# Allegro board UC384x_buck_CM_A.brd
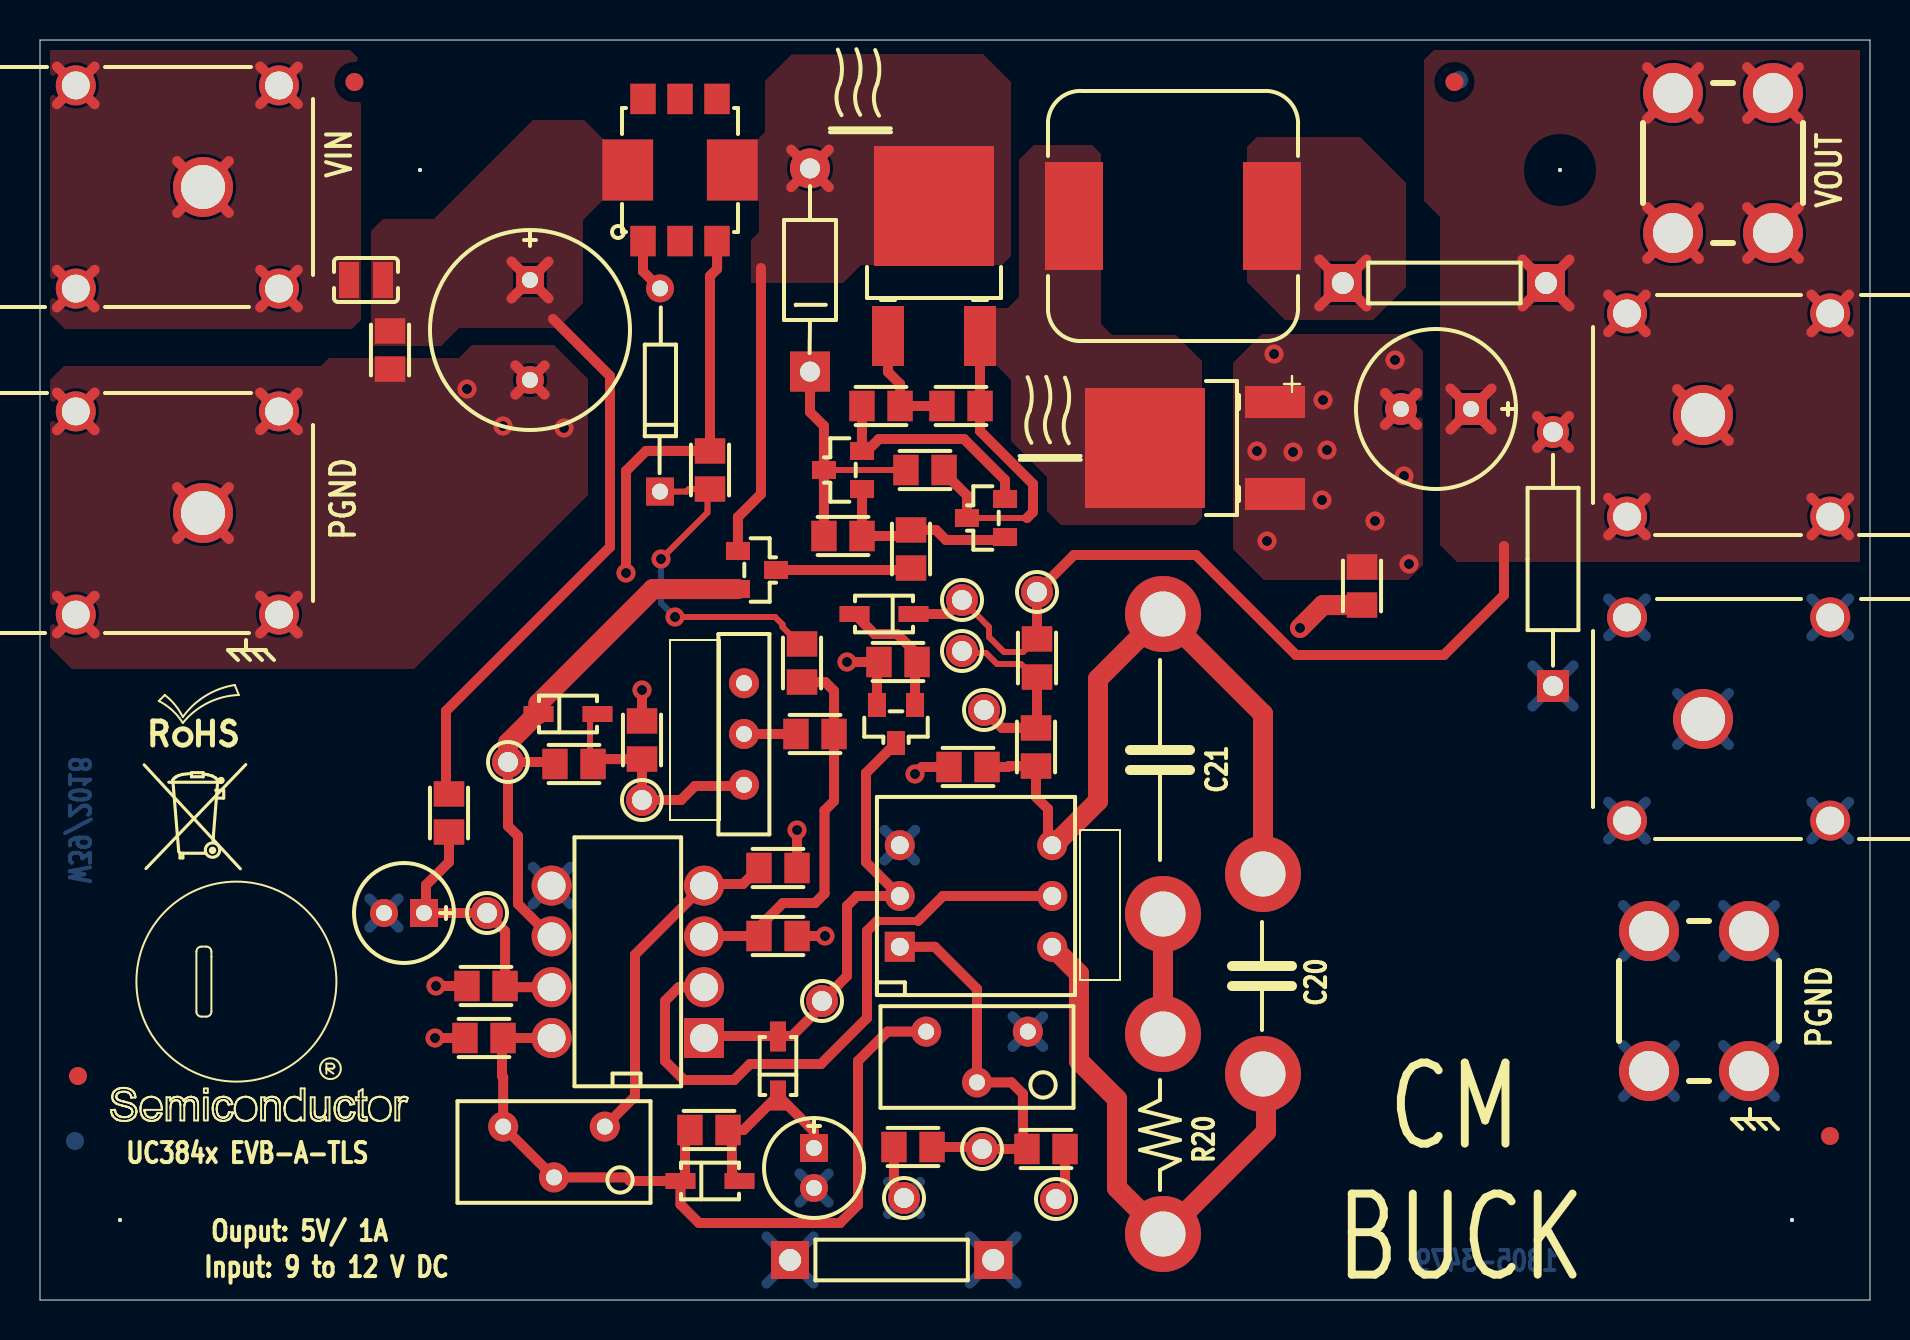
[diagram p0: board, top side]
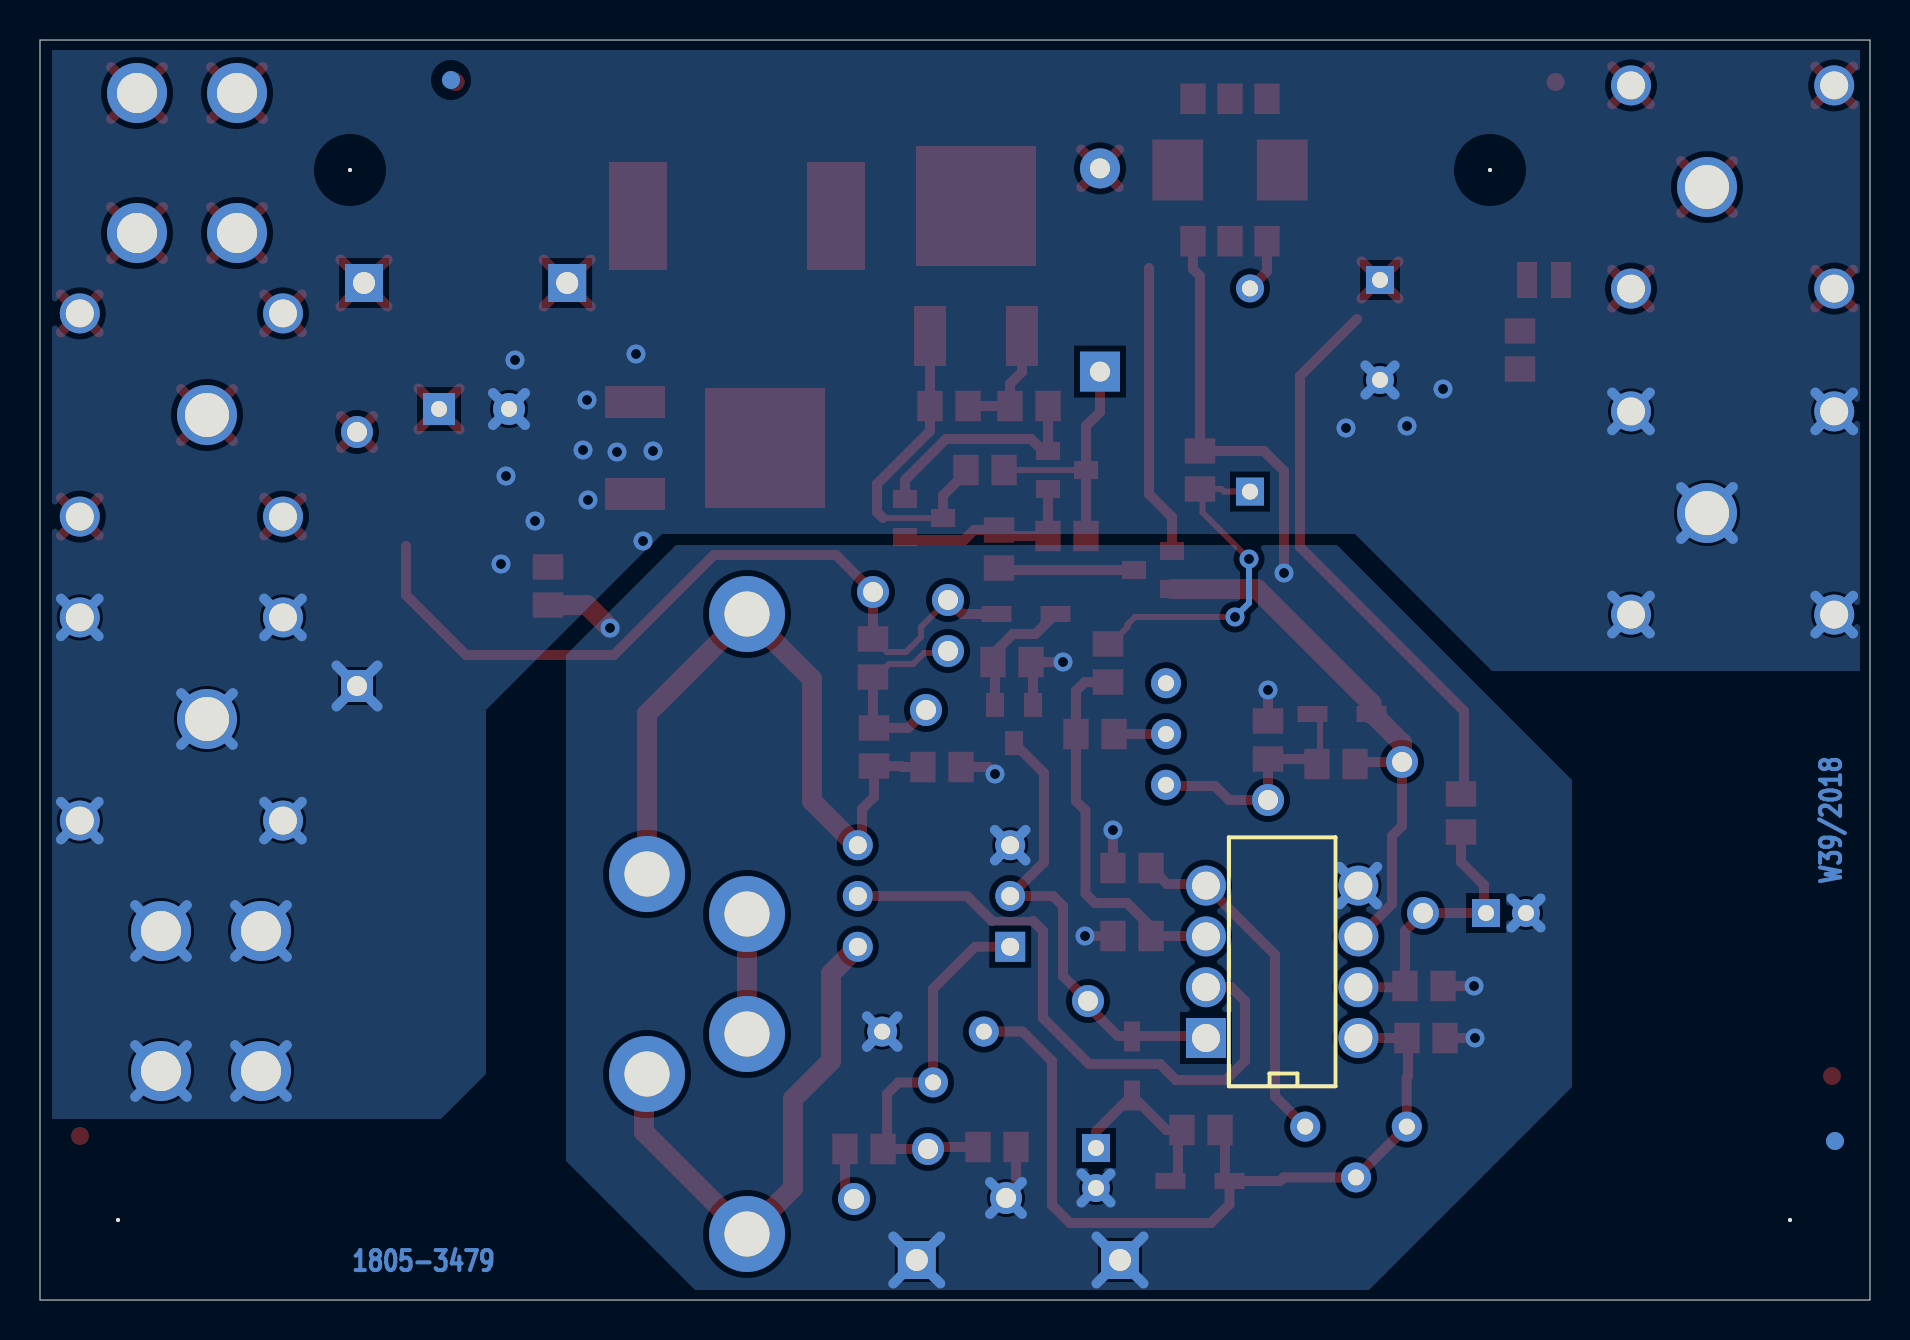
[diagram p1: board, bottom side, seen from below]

Outline 91.5 x 63 mm; copper layers: TOP, IN1, IN2, BOTTOM. Coordinates in mm from the lower left corner of the outline.
Outline path: 0,63 0,0 91.5,0 91.5,63 0,63

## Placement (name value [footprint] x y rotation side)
ACM_H  TEST POINT  [TP]  50.8 5.05 180 top
ACM_L  TEST POINT  [TP]  43.2 5.1 180 top
C1  100nF  [0805]  22.2 13.1 180 top
C1A  D  [PLOT_5380598-2]  56.15 34.3 270 top
C1B  D  [PLOT_5380598-2]  56.15 19.3 270 top
C2  2.2nF  [0805]  36.9 21.6 0 top
C2A  D  [PLOT_5380598-2]  61.15 21.3 270 top
C2B  D  [PLOT_5380598-2]  61.15 11.3 270 top
C3  2.2uF  [CAPA_CH_D5_H11_P2]  18.2 19.35 180 top
C6  220uF  [CAPA_CH_D8_H12_P3V5]  69.8 44.55 180 top
C7  100nF  [0805]  22.3 15.7 180 top
C8  100nF  [0805]  43.65 7.65 180 top
C9  2.2uF  [0805]  50.3 7.55 180 top
C10  100pF  [0805]  36.9 18.2 0 top
C11  2.2nF  [0805]  30.1 28 90 top
C12  100uF /6v3  [CAPA_CH_D5_H11_P2]  38.7 6.6 270 top
C13  470uF  [CAPA_CH_D10_H13_P5]  24.5 48.5 270 top
C14  1uF  [0805]  17.5 47.5 270 top
C18  0.1uF  [0805]  44.25 41.5 0 top
CB1  target_cms  [MIRE_LOW]  1.75 7.95 180 bottom
CB2  target_cms  [MIRE_LOW]  70.95 61 180 bottom
CB3  target_cms  [MIRE_LOW]  1.9 11.2 0 top
CB4  target_cms  [MIRE_LOW]  70.72 60.9 0 top
CB5  target_cms  [MIRE_LOW]  89.5 8.2 0 top
CB6  target_cms  [MIRE_LOW]  15.72 60.9 0 top
COMP  TEST POINT  [TP]  39.1 14.95 180 top
D1  1N4148w  [SOD123]  26.4 29.3 0 top
D2  1N4148w  [SOD123]  33.5 5.95 0 top
D3  MBRD1045T4G  [DPAK_TO252]  56.85 42.6 90 top
D4  1N4148w  [SOD123]  36.9 11.7 90 top
D6  MMSZ6V2T1G  [SOD123]  42.2 34.3 180 top
D7  1N965  [DO35]  31 45.5 90 top
D8  1N5817  [DO41]  38.5 51.5 90 top
DRV  TEST POINT  [TP]  23.4 26.9 180 top
J1A  SLB4-I/90_R  [BANANE_4MM_SLB4]  8.15 55.65 180 top
J1B  SLB4-I/90_B  [BANANE_4MM_SLB4]  8.15 39.35 180 top
J1C  SLB4-I/90_R  [BANANE_4MM_SLB4]  83.15 44.25 0 top
J1D  SLB4-I/90_B  [BANANE_4MM_SLB4]  83.15 29.05 0 top
J2A  Screw_terminal  [PC_7701]  84.15 56.85 0 top
J2B  Screw_terminal  [PC_7701]  82.95 14.95 0 top
L1  100uH-1.7A  [SELF_WE-PD-1260]  56.65 54.2 90 top
L2  2.2uH  [SELF_SRN2009]  16.3 51 0 top
NOREF  -  [unnamed]  87.6 4 0 top
NOREF#2  -  [#2]  91.5 0 90 top
NOREF#3  -  [unnamed]  4 4 0 top
NOREF#4  -  [#2]  0 63 0 top
NOREF#5  -  [unnamed]  76 56.5 0 top
NOREF#6  -  [#2]  91.5 0 90 top
NOREF#7  -  [#2]  -181.6 -74.35 0 top
NOREF#8  -  [#2]  -114.15 -47.45 0 top
NOREF#9  -  [#2]  87.6 4 0 top
NOREF#10  -  [unnamed]  19 56.5 0 top
NOREF#11  -  [#2]  283.55 -63.75 180 bottom
P1  10K  [POTAR_12T_3266W]  46.85 12.15 180 top
P2  20K  [POTAR_12T_3266W]  25.7 7.4 180 top
Q1  NTD5865NLT4G  [DPAK_TO252]  44.7 53.1 0 top
Q2  MMBT2222A  [SOT23]  42.8 28.8 0 top
Q3  MMBT2222A  [SOT23]  40.15 41.5 270 top
Q6  MMBT2907A  [SOT23]  47.3 39.1 270 top
Q7  BSS138LT1G  [SOT23]  35.85 36.5 90 top
R1  10K  [0805]  49.8 27.65 90 top
R2  4.7K  [0805]  38.1 31.85 270 top
R2A  D  [PLOT_5380598-2]  56.15 13.3 270 top
R2B  D  [PLOT_5380598-2]  56.15 3.3 270 top
R3  60  [0805]  33.5 41.5 270 top
R4  22K  [0805]  26.7 26.8 0 top
R5  10R  [0805]  20.45 24.35 90 top
R6  33K  [0805]  38.75 28.3 180 top
R7  10K  [0805]  46.4 26.65 0 top
R8  10R  [0805]  49.85 32.1 90 top
R11  0R  [0805]  66.1 35.7 90 top
R12  1K / 0.5W  [RC21U]  75.65 37.05 90 top
R13  1.5K  [0805]  33.45 8.5 180 top
R14  1K  [0805]  42.9 31.9 0 top
R15  47K  [0805]  46.05 44.7 180 top
R16  10R  [0805]  42.05 44.7 0 top
R17  2.2K  [0805]  40.15 38.2 0 top
R18  100  [0805]  43.55 37.55 270 top
RAMP  TEST POINT  [TP]  30.1 25 180 top
S1  Strap  [JUMPER400H]  75.3 50.85 180 top
S2  Strap  [JUMPER400H]  37.5 2 0 top
SW1  DPDT  [SW_76SD01ST]  46.8 20.2 0 top
SW2  DPDT  [SWITCH-1K2]  35.2 28.3 90 top
T1  KMP_53100C  [MURATA_5300]  32 56.5 0 top
U1  UC3845B  [DIP8_SUP]  33.2 13.1 180 top
VA  TEST POINT  [TP]  47.2 29.5 0 top
VA_  TEST POINT  [TP]  46.1 32.45 0 top
VB  TEST POINT  [TP]  49.85 35.4 0 top
VB_  TEST POINT  [TP]  46.1 35 0 top
VCC  TEST POINT  [TP]  22.35 19.35 180 top
VSET  TEST POINT  [TP]  47.1 7.55 180 top

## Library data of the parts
ACM_H ACM_L COMP DRV RAMP S1 S2 VA VA_ VB VB_ VCC VSET = TEST POINT_0
C1 C2 C7-C11 C14 C18 = C
C1A C1B C2A C2B R2A R2B = T POINT R_0
C3 C12 = CAP POL
C6 C13 = C_elect_0
CB1-CB6 = target_cms
D1 = D1N4148_1
D2 D4 = D1N4148_2
D3 = dual_diodeAAK
D6 = DIODE SCHOTTKY_0
D7 = 1N965_0
D8 = 1N5817_0
J1A J1B J1C J1D = HEADER 1_0
J2A J2B = 4 HEADER_0
L1 = CHOKE
L2 = L
P1 P2 = RESISTOR VAR
Q1 = NMOS_2
Q2 Q3 = 2N2222A_0
Q6 = 2N2907A_0
Q7 = NMOS_1
R1-R8 R11-R18 = R
SW1 = SW DPDT/SM_0
SW2 = SW SPST
T1 = KMP_0
U1 = UC3845B

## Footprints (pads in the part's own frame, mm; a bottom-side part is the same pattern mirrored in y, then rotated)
0805
  rect 1.27x1.524 smd: 1(-0.953,0) 2(0.953,0)
BANANE_4MM_SLB4
  round 3 hole 2.2: 1(0,0)
  round 2 hole 1.4: 2(-3.8,5.08) 3(-3.8,-5.08) 4(6.36,5.08) 5(6.36,-5.08)
CAPA_CH_D5_H11_P2
  rect 1.4x1.4 hole 0.8: 1(-1,0)
  round 1.4 hole 0.8: 2(1,0)
CAPA_CH_D8_H12_P3V5
  rect 1.6x1.6 hole 0.8: 1(-1.75,0)
  round 1.6 hole 0.8: 2(1.75,0)
CAPA_CH_D10_H13_P5
  rect 1.4x1.4 hole 0.8: 1(-2.5,0)
  round 1.4 hole 0.8: 2(2.5,0)
DIP8_SUP
  rect 2x2 hole 1.4: 1(0,0)
  round 2 hole 1.4: 2(0,-2.54) 3(0,-5.08) 4(0,-7.62) 5(7.62,-7.62) 6(7.62,-5.08) 7(7.62,-2.54) 8(7.62,0)
DO35
  rect 1.4x1.4 hole 0.8: 1(-5.08,0)
  round 1.4 hole 0.8: 2(5.08,0)
DO41
  rect 2x2 hole 1: 1(-5.08,0)
  round 2 hole 1: 2(5.08,0)
DPAK_TO252
  rect 1.6x3 smd: 1(-2.3,-4.9) 3(2.3,-4.9)
  rect 6x6 smd: 2(0,1.6)
JUMPER400H
  rect 1.9x1.9 hole 1.1: 1(0,0) 2(10.16,0)
MIRE_LOW
  round 0.9 smd: 1(0,0)
MURATA_5300
  rect 1.27x1.524 smd: 1(-1.85,-3.555) 2(0,-3.555) 3(1.85,-3.555) 4(1.85,3.555) 5(0,3.555) 6(-1.85,3.555)
  rect 2.54x3.05 smd: 7(2.615,0) 8(-2.615,0)
PC_7701
  round 3 hole 2: 1(-2.5,-3.5) 2(2.5,-3.5) 3(2.5,3.5) 4(-2.5,3.5)
PLOT_5380598-2
  round 3.8 hole 2.25: 1(0,0)
POTAR_12T_3266W
  round 1.5 hole 0.8: 1(-2.54,-1.27) 2(0,1.27) 3(2.54,-1.27)
RC21U
  rect 1.6x1.6 hole 1: 1(-6.35,0)
  round 1.6 hole 1: 2(6.35,0)
SELF_SRN2009
  rect 1x1.8 smd: 1(-0.85,0) 2(0.85,0)
SELF_WE-PD-1260
  rect 5.4x2.9 smd: 1(0,4.95) 2(0,-4.95)
SOD123
  rect 1.5x0.8 smd: 1(-1.475,0) 2(1.475,0)
SOT23
  rect 0.9x1.2 smd: 1(0.953,0.953) 2(-0.953,0.953) 3(0,-0.953)
SW_76SD01ST
  rect 1.5x1.5 hole 0.9: 1(-3.81,-2.54)
  round 1.5 hole 0.9: 2(-3.81,2.54) 11(3.81,-2.54) 22(3.81,2.54) C1(-3.81,0) C2(3.81,0)
SWITCH-1K2
  round 1.5 hole 0.8: 1(-2.54,0) 2(0,0) 3(2.54,0)
TP
  round 1.6 hole 1: 1(0,0)
unnamed
  round 0.2 hole 3 unplated: (0,0)

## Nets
GND_EARTH: ACM_L.1 C1.2 C2.2 C3.2 C7.2 C8.2 C10.2 C11.2 C12.2 P1.1(A) Q2.2(EMITTER) R3.1 R7.1 R11.1 R14.1 S2.1 S2.2 SW1.2(NO2) T1.3 U1.5(GND)
GND_SIGNAL: C6.2(-) C13.2(-) C14.2 D3.1(A1) D3.3(A2) J1B.1 J1B.2 J1B.3 J1B.4 J1B.5 J1D.1 J1D.2 J1D.3 J1D.4 J1D.5 J2B.1 J2B.2 J2B.3 J2B.4 R11.2 R12.1
VCC: C3.1 C7.1 R5.1 U1.7(VCC) VCC.1
CMP: COMP.1 D4.2 Q2.3(COLLECTOR) SW1.C1(COMMON1) U1.1(EA)
DRV: D1.1 DRV.1 Q7.2(S) R4.1 U1.6(DRV)
REF: C1.1 D2.1 P1.3(B) P2.2(WIPER) P2.3(B) R13.2 U1.8(REF)
VOUT: C6.1(+) D6.1(CATHODE) J1C.1 J1C.2 J1C.3 J1C.4 J1C.5 J2A.1 J2A.2 J2A.3 J2A.4 R8.2 R12.2 S1.1 VB.1 VB_.1
N12289703: C13.1(+) C14.1 L2.2 R5.2 T1.8
N12295463: C2.1 P2.1(A) U1.4(RT/CT)
N12295845: C10.1 R2.2 R6.1 U1.3(IS)
N12296076: D7.1(CATHODE) R2.1 R3.2
N12296104: SW1.C2(COMMON2) U1.2(FB)
N12296437: C11.1 D1.2 R4.2 RAMP.1 SW2.1
N12297349: R1.2 R8.1 VA.1 VA_.1
N12298127: C1A.1(TP) C2A.1(TP) R1.1 R7.2 SW1.22(NC2)
N12298463: C8.1 C9.2 P1.2(WIPER) SW1.1(NO1) VSET.1
N12299817: C1B.1(TP) R2A.1(TP)
N12299821: C2B.1(TP) R2B.1(TP) SW1.11(NC1)
N12301916: ACM_H.1 C9.1
N12517793: J1A.1 J1A.2 J1A.3 J1A.4 J1A.5 L2.1
N12518756: D8.2 Q1.2(D) Q7.1(G) T1.7
N12518780: Q7.3(D) R18.2
N12519113: D7.2(ANODE) T1.1
N12519598: Q3.1(BASE) Q6.1(BASE) R17.2 R18.1
N12520738: C18.1 D8.1 Q3.3(COLLECTOR) R17.1
N12521657: Q3.2(EMITTER) Q6.2(EMITTER) R16.1
N12521671: Q1.1(G) R15.2 R16.2
N12521759: C18.2 D3.2(C) L1.1 Q1.3(S) Q6.3(COLLECTOR) R15.1
N12522225: L1.2 S1.2
N12524308: C12.1 D2.2 D4.1 R13.1
N12524692: D6.2(ANODE) Q2.1(BASE) R14.2
N122961380: R6.2 SW2.2

Pads without a net: CB1 1; CB2 1; CB3 1; CB4 1; CB5 1; CB6 1; SW2 3; T1 2 4 5 6

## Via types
v1: diameter 0.95, hole 0.5, TOP to BOTTOM, 25 vias

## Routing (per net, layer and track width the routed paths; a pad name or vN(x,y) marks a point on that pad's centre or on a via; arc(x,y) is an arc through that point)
GND_EARTH: length 80.3
  TOP w0.5: C1.2 v1(19.75,13.1) ; C10.2 v1(39.25,18.2) ; Q2.2 41.85,31.8 R14.1 v1(40.35,31.9) ; C2.2 v1(37.85,23.5) ; R7.1 44.1,26.65 v1(43.75,26.3) ; ACM_L.1 42.7,5.6 C8.2 ; v1(29.3,36.35) 29.3,41.45 30.3,42.45 R3.1 33.5,51.2 33.85,51.55 33.85,52.94 T1.3 ; C11.2 v1(30.1,30.5) ; C7.2 v1(19.8,15.7)
  TOP w1: v1(63,33.6) 64.15,34.75 R11.1
  BOTTOM w0.5: 24.64,21.66 U1.5 ; U1.5 26.52,19.78 ; U1.5 26.52,21.66 ; U1.5 24.64,19.78 ; ACM_L.1 44,4.3 ; ACM_L.1 42.4,4.3 ; ACM_L.1 42.4,5.9 ; ACM_L.1 44,5.9 ; C12.2 39.43,6.33 ; C12.2 37.97,4.87 ; C12.2 37.97,6.33 ; C12.2 39.43,4.87 ; 48.63,12.66 P1.1 ; P1.1 50.15,12.66 ; P1.1 48.63,14.18 ; P1.1 50.15,14.18 ; 42.23,21.98 SW1.2 ; SW1.2 43.75,23.5 ; SW1.2 43.75,21.98 ; SW1.2 42.23,23.5 ; S2.2 48.84,3.18 ; S2.2 46.48,0.82 ; S2.2 48.84,0.82 ; S2.2 46.48,3.18 ; 36.32,3.18 S2.1 ; S2.1 38.68,0.82 ; S2.1 38.68,3.18 ; S2.1 36.32,0.82 ; 16.47,18.62 C3.2 ; C3.2 17.93,18.62 ; C3.2 16.47,20.08 ; C3.2 17.93,20.08
GND_SIGNAL: length 138.3
  TOP w0.5: 67.25,45.35 C6.2 ; C6.2 68.85,45.35 ; C6.2 67.25,43.75 ; C6.2 68.85,43.75 ; J1B.5 2.73,43.49 ; J1B.5 2.73,45.37 ; J1B.5 0.85,43.49 ; J1B.5 0.85,45.37 ; J1B.4 2.73,35.21 ; J1B.4 0.85,35.21 ; J1B.4 0.85,33.33 ; J1B.4 2.73,33.33 ; 11.01,43.49 J1B.3 ; J1B.3 12.89,43.49 ; J1B.3 12.89,45.37 ; J1B.3 11.01,45.37 ; 11.01,35.21 J1B.2 ; J1B.2 11.01,33.33 ; J1B.2 12.89,33.33 ; J1B.2 12.89,35.21 ; J1B.1 9.44,38.06 ; J1B.1 6.86,40.64 ; J1B.1 9.44,40.64 ; J1B.1 6.86,38.06 ; 23.77,45.27 C13.2 ; C13.2 23.77,46.73 ; C13.2 25.23,46.73 ; C13.2 25.23,45.27
  BOTTOM w0.5: J1B.5 2.73,45.37 ; J1B.5 2.73,43.49 ; J1B.5 0.85,43.49 ; J1B.5 0.85,45.37 ; 78.41,33.19 J1D.2 ; J1D.2 80.29,33.19 ; J1D.2 80.29,35.07 ; J1D.2 78.41,35.07 ; J1B.4 2.73,33.33 ; J1B.4 0.85,33.33 ; J1B.4 0.85,35.21 ; J1B.4 2.73,35.21 ; 88.57,24.91 J1D.5 ; J1D.5 88.57,23.03 ; J1D.5 90.45,23.03 ; J1D.5 90.45,24.91 ; 79.16,12.74 J2B.1 ; J2B.1 81.74,10.16 ; J2B.1 81.74,12.74 ; J2B.1 79.16,10.16 ; 11.01,35.21 J1B.2 ; J1B.2 12.89,35.21 ; J1B.2 11.01,33.33 ; J1B.2 12.89,33.33 ; J1D.3 80.29,24.91 ; J1D.3 78.41,24.91 ; J1D.3 78.41,23.03 ; J1D.3 80.29,23.03 ; J1D.1 84.44,30.34 ; J1D.1 81.86,30.34 ; J1D.1 81.86,27.76 ; J1D.1 84.44,27.76 ; 79.16,17.16 J2B.4 ; J2B.4 81.74,17.16 ; J2B.4 81.74,19.74 ; J2B.4 79.16,19.74 ; 84.16,17.16 J2B.3 ; J2B.3 86.74,19.74 ; J2B.3 86.74,17.16 ; J2B.3 84.16,19.74 ; J1B.3 12.89,45.37 ; J1B.3 12.89,43.49 ; J1B.3 11.01,43.49 ; J1B.3 11.01,45.37 ; 74.62,29.67 R12.1 ; R12.1 76.68,29.67 ; R12.1 74.62,31.73 ; R12.1 76.68,31.73 ; J1D.4 90.45,33.19 ; J1D.4 90.45,35.07 ; J1D.4 88.57,33.19 ; J1D.4 88.57,35.07 ; C6.2 68.85,45.35 ; C6.2 68.85,43.75 ; C6.2 67.25,45.35 ; C6.2 67.25,43.75 ; 23.77,46.73 C13.2 ; C13.2 25.23,45.27 ; C13.2 25.23,46.73 ; C13.2 23.77,45.27 ; J2B.2 86.74,10.16 ; J2B.2 84.16,10.16 ; J2B.2 84.16,12.74 ; J2B.2 86.74,12.74 ; J1B.1 9.44,40.64 ; J1B.1 6.86,38.06 ; J1B.1 6.86,40.64 ; J1B.1 9.44,38.06
  vias: v1(21.35,45.55) v1(23.15,43.7) v1(26.2,43.6) v1(60.85,42.45) v1(61.35,37.95) v1(61.7,47.3) v1(62.65,42.4) v1(64.1,40) v1(64.15,45) v1(64.35,42.5) v1(66.75,38.95) v1(67.75,47) v1(68.2,41.2) v1(68.45,36.8)
VCC: length 14.1
  TOP w0.5: U1.7 23.31,15.64 C7.1 23.25,18.45 VCC.1 C3.1 19.3,19.45 19.3,20.75 20.45,21.9 R5.1
CMP: length 23.9
  TOP w0.5: 36.88,13.2 33.3,13.2 U1.1 ; 36.88,13.2 37.6,13.2 39.1,14.7 COMP.1 40.35,16.2 40.35,19.7 40.85,20.2 SW1.C1 41.3,21.89 41.3,26.35 Q2.3 ; 36.88,13.2 36.9,13.18
DRV: length 28
  TOP w0.5: U1.6 25.52,18.18 23.9,19.8 23.9,23.2 23.4,23.7 DRV.1 25.65,26.9 R4.1
  TOP w1: Q7.2 30.65,35.55 24.93,29.82 D1.1 24.85,29.3 23.4,27.85 DRV.1
REF: length 41.7
  TOP w0.5: U1.8 C1.1 23.1,13.05 23.1,11.2 23.16,11.14 P2.3 P2.2 29.32,6.13 29.5,5.95 D2.1 ; D2.1 32.25,6.18 32.25,8.25 R13.2 ; D2.1 32.02,4.78 32.95,3.85 40,3.85 40.9,4.75 40.9,11.95 42.37,13.42 P1.3
VOUT: length 115.2
  TOP w0.3: R8.2 49.8,33.05 49.15,32.4 48.2,32.4 47.45,33.15 47.45,33.65 VB_.1
  TOP w0.5: 74.12,49.67 S1.1 ; S1.1 74.12,52.03 ; S1.1 76.48,52.03 ; S1.1 76.48,49.67 ; J1C.1 84.44,42.96 ; J1C.1 81.86,42.96 ; J1C.1 81.86,45.54 ; J1C.1 84.44,45.54 ; 88.57,48.39 J1C.4 ; J1C.4 90.45,48.39 ; J1C.4 88.57,50.27 ; J1C.4 90.45,50.27 ; J2A.1 82.94,54.64 ; J2A.1 82.94,52.06 ; J2A.1 80.36,52.06 ; J2A.1 80.36,54.64 ; R12.2 76.45,44.2 ; R12.2 74.85,42.6 ; R12.2 74.85,44.2 ; R12.2 76.45,42.6 ; 70.52,45.58 C6.1 ; C6.1 72.58,45.58 ; C6.1 72.58,43.52 ; C6.1 70.52,43.52 ; 85.36,52.06 J2A.2 ; J2A.2 87.94,54.64 ; J2A.2 87.94,52.06 ; J2A.2 85.36,54.64 ; 78.41,48.39 J1C.2 ; J1C.2 80.29,50.27 ; J1C.2 78.41,50.27 ; J1C.2 80.29,48.39 ; 78.41,40.11 J1C.3 ; J1C.3 78.41,38.23 ; J1C.3 80.29,38.23 ; J1C.3 80.29,40.11 ; J2A.3 87.94,59.06 ; J2A.3 85.36,59.06 ; J2A.3 85.36,61.64 ; J2A.3 87.94,61.64 ; 80.36,61.64 J2A.4 ; J2A.4 80.36,59.06 ; J2A.4 82.94,59.06 ; J2A.4 82.94,61.64 ; 88.57,38.23 J1C.5 ; J1C.5 90.45,40.11 ; J1C.5 88.57,40.11 ; J1C.5 90.45,38.23 ; 73.2,37.7 73.2,35.25 70.2,32.25 62.8,32.25 57.8,37.25 51.7,37.25 VB.1 R8.2 ; VB_.1 45.4,34.3 D6.1
N12289703: length 33.6
  TOP w0.5: 25.65,49.05 28.5,46.2 28.5,37.65 20.3,29.45 20.3,25.45 R5.2 ; C13.1 25.43,50.07 ; C13.1 23.57,51.93 ; C13.1 23.57,50.07 ; C13.1 25.43,51.93
N12295463: length 17.2
  TOP w0.5: C2.1 35.15,20.8 33.28,20.8 U1.4 29.75,17.27 29.75,10.18 P2.1
N12295845: length 19.4
  TOP w0.5: 35.7,18.2 33.22,18.2 U1.3 ; 35.7,18.2 C10.1 ; 35.7,18.2 35.7,18.4 37.15,19.85 38.75,19.85 39.23,20.33 39.23,24.48 39.7,24.95 R6.1 39.7,30.46 39.26,30.9 R2.2
N12296076: length 17.2
  TOP w0.3: v1(31.05,37.05) 33.37,39.37 33.37,40.55 ; D7.1 32.31,40.42 32.44,40.55 33.37,40.55 ; R3.2 33.37,40.55 ; R2.1 37.97,32.8 37.13,33.65 37.13,33.78 36.75,34.15 v1(31.75,34.15)
  BOTTOM w0.3: v1(31.05,37.05) 31.05,34.85 v1(31.75,34.15)
N12296104: length 31.3
  TOP w0.4: 41.85,18.95 43.9,18.95
  TOP w0.5: U1.2 31.94,15.64 31.25,14.95 31.25,11.95 32.2,11 34.7,11 35.5,11.8 39.05,11.8 41.35,14.1 41.35,18.45 41.85,18.95 ; 43.9,18.95 45.15,20.2 SW1.C2
N12296437: length 12.7
  TOP w0.3: R4.2 27.5,26.95 27.5,28.93 D1.2
  TOP w0.5: SW2.1 35.14,25.7 32.75,25.7 32.05,25 RAMP.1 C11.1 27.9,27.05 R4.2
N12297349: length 9.8
  TOP w0.3: VA_.1 46.2,32.35 47.3,32.35 47.85,31.8 49.05,31.8 49.7,31.15 R8.1
  TOP w0.5: VA.1 48.1,28.6 R1.2 49.85,28.65 R8.1
N12298127: length 35.7
  TOP w0.5: SW1.22 50.4,22.95 50.4,24.55 49.8,25.15 R1.1 48.44,26.7 48.39,26.65 R7.2
  TOP w1: SW1.22 50.69,22.74 52.9,24.95 52.9,31.05 C1A.1 61.15,29.3 C2A.1
N12298463: length 19.6
  TOP w0.5: C9.2 49.15,7.75 49.15,10.3 48.57,10.88 P1.2 46.85,15.55 44.74,17.66 SW1.1 ; C9.2 49.39,7.59 ; C9.2 VSET.1 47,7.65 C8.1
N12299817: length 6
  TOP w1: C1B.1 R2A.1
N12299821: length 26.9
  TOP w1: SW1.11 51.95,16.32 51.95,11.95 53.85,10.05 53.85,5.6 R2B.1 56.2,3.3 61.3,8.4 61.3,11.15 C2B.1
N12301916: length 2.7
  TOP w0.5: ACM_H.1 51.25,5.5 C9.1
N12517793: length 28.6
  TOP w0.5: 11.01,49.63 J1A.2 ; J1A.2 12.89,51.51 ; J1A.2 12.89,49.63 ; J1A.2 11.01,51.51 ; J1A.4 2.73,51.51 ; J1A.4 0.85,49.63 ; J1A.4 0.85,51.51 ; J1A.4 2.73,49.63 ; J1A.5 2.73,59.79 ; J1A.5 2.73,61.67 ; J1A.5 0.85,61.67 ; J1A.5 0.85,59.79 ; 11.01,61.67 J1A.3 ; J1A.3 11.01,59.79 ; J1A.3 12.89,59.79 ; J1A.3 12.89,61.67 ; 6.86,56.94 J1A.1 ; J1A.1 9.44,56.94 ; J1A.1 6.86,54.36 ; J1A.1 9.44,54.36
N12518756: length 19.9
  TOP w0.5: D8.2 39.44,55.64 ; D8.2 37.56,57.52 ; D8.2 37.56,55.64 ; D8.2 39.44,57.52 ; 36.05,51.6 36.05,40.3 34.9,39.15 Q7.1
N12518780: length 6.8
  TOP w0.5: Q7.3 43.45,36.5 R18.2
N12519113: length 2.7
  TOP w0.5: D7.2 30.15,51.43 T1.1
N12519598: length 9.9
  TOP w0.5: Q6.1 48.1,38 45.3,38 44.8,38.5 R18.1 43.4,38.5 43.1,38.2 R17.2 Q3.1
N12520738: length 12.6
  TOP w0.3: C18.1 Q3.3
  TOP w0.5: D8.1 38.5,44.4 39.2,43.7 Q3.3 R17.1
N12521657: length 11.4
  TOP w0.5: R16.1 41.1,42.46 Q3.2 41.35,42.45 41.95,43.05 46.2,43.05 48.25,41 Q6.2
N12521671: length 5.8
  TOP w0.5: R15.2 R16.2 43,45.8 42.4,46.4 Q1.1
N12521759: length 16.2
  TOP w0.3: Q6.3 49.35,39.1
  TOP w0.5: Q1.3 47,44.7 R15.1 47,43.45 49.65,40.8 49.65,39.4 49.35,39.1 ; Q6.3 46.35,40.23 45.2,41.37 C18.2
N12522225: length 6.6
  TOP w0.5: 63.96,52.03 S1.2 ; S1.2 63.96,49.67 ; S1.2 66.32,49.67 ; S1.2 66.32,52.03
N12524308: length 9.4
  TOP w0.5: C12.1 38.7,8.43 D4.1 35.17,8.5 R13.1 34.6,8.3 34.6,6.32 D2.2
N12524692: length 6.5
  TOP w0.5: D6.2 41.73,33.3 42.85,33.3 43.85,32.3 R14.2 43.75,31.8 Q2.1
N122961380: length 2.6
  TOP w0.5: R6.2 SW2.2

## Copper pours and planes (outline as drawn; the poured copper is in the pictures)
GND_EARTH on BOTTOM: 25.05,0.5 14.9,10.65 14.9,26 26.65,37.75 59.7,37.75 65.2,32.25 65.2,6.95 58.75,0.5
GND_SIGNAL on TOP: 69.15,36.75 69.15,47.45 68.3,48.3 61.1,48.3 59.65,46.85 59.65,37.55 61.2,36 68.4,36
GND_SIGNAL on TOP: 1.6,31.55 0.5,32.65 0.5,46 1.2,46.7 14.05,46.7 14.45,47.1 20.95,47.1 21.6,47.75 25.7,47.75 27.4,46.05 27.4,40.25 18.7,31.55
GND_SIGNAL on BOTTOM: 71.45,9.05 69.2,11.3 69.2,29.5 60.4,38.3 25.75,38.3 18.9,31.45 0.5,31.45 0.5,62.5 90.9,62.5 90.9,9.05
Net_36 on IN2: 0,0 0,53 83.5,53 83.5,0
VOUT on TOP: 70.85,36.9 70,37.75 70,54.15 69.2,54.95 69.2,62 69.7,62.5 91,62.5 91,36.95 90.95,36.9
N12289703 on TOP: 20.1,47.7 16.55,47.7 16.55,53.45 17.15,54.05 19.7,54.05 24.65,59 27.2,59 28.6,57.6 29.9,57.6 30.25,57.25 30.25,55.9 29.5,55.15 28.3,55.15 27.15,54 27.15,49.85 25.9,48.6 20.95,48.6 20.1,47.75
N12517793 on TOP: 1.25,48.55 0.5,49.3 0.5,62.5 15.5,62.5 16.05,61.95 16.05,49 15.6,48.55
N12518756 on TOP: 33.45,57.9 33.45,55.8 33.85,55.4 35.45,55.4 35.95,54.9 35.95,53.4 35.55,53 35.55,50.85 40.15,50.85 41.05,51.75 48.1,51.75 48.55,52.2 48.55,60.9 47.15,62.3 40.15,62.3 40.12,62.28 37.58,62.28 36.25,60.95 36.25,58.4 35.75,57.9
N12521759 on TOP: 46.35,49.6 48.4,49.6 48.95,50.15 48.95,57 49.7,57.75 52.6,57.75 53.05,57.3 53.05,48.8 53.6,48.25 56.8,48.25 58.1,46.95 58.1,39.1 57.75,38.75 51.05,38.75 50.35,39.45 50.35,41.15 48.55,42.95 48.55,46 47.65,46.9 46.5,46.9 46.45,46.85 46.35,46.95
N12522225 on TOP: 60.85,58.15 66,58.15 68.3,55.85 68.3,50.65 66.65,49 62.25,49 60.35,50.9 60.35,57.65

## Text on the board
BOTTOM: BOT 1/1 | 1805-3479 | W39/2018
Ref Des/Silkscreen Bottom: SILK_BOT
User.Comments: VE_BOT | VE_TOP
TOP: TOP 2/2
Ref Des/Silkscreen Top: UC384x EVB-A-TLS | Input: 9 to 12 V DC | Ouput: 5V/ 1A | R20 | C21 | C20 | SILK_TOP | VIN | PGND | VOUT | BUCK | CM
IN1: IN1 3/4
IN2: IN2 2/4
DIMENSION: 1.0 | CM BUCK
BODY_CENTER: 1.0
User.5: CHEMICAL NiAu | 35um(1oz)at START | THICKNESS | MATERIAL | STACKUP | FINISH | SILKSCREEN | MINIMAL GAP | MINIMAL SLIVER | BOARD THICKNESS | SOLDER MASK | COPPER THICKNESS | MARKED ON BOTTOM SOLDERMASK | ALL BOARD ELECTRICALLY TESTED | MANUFACTURE 'S LOGO & DATECODE | COMPLIANT RoHS DIRECTIVE 2011/65/UE | DF /2LAYERS | WHITE TOP | FR4 IMPROVED (low CTE) | VIA | 210um /8.0mils | GREEN TOP & BOT | 1.6mm /63mils | 1.0 | CM BUCK | SPEC:
User.6: DEMO UC384x CM-buck 1805-3479   W34/2018
User.7: FIGURE | SIZE | 0.5 | 0.8 | 0.9 | 1.0 | 1.1 | 1.4 | 2.0 | 2.2 | 2.25 | 3.0 | DRILL CHART: TOP to BOTTOM | ALL UNITS ARE IN MILLIMETERS | TOLERANCE | +0.0/-0.0 | +0.1/-0.05 | +0.05/-0.05 | +0.1/-0.1 | PLATED | NON-PLATED | QTY | 25 | 19 | 6 | 15 | 4 | 24 | 8
